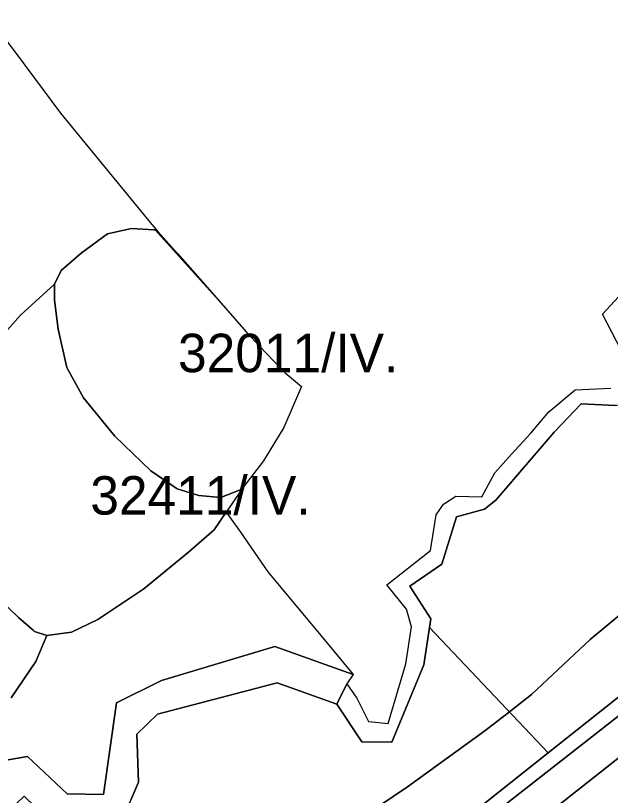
# Model space of a CAD drawing. Extents: x -522079 to -518792, y -1142400 to -1139961.
# Drawn here: x -521597.2 to -521365.3, y -1140523.8 to -1140219.9 of the extents above; entities that cross this region are included whole.
import ezdxf

# ---------------------------------------------------------------- set-up
doc = ezdxf.new("R2010")
doc.units = 0
for name, color, linetype in [('Hranice parcel', 7, 'Continuous'), ('Parcelní čísla', 7, 'Continuous'), ('Poz předměty', 7, 'Continuous'), ('Vnitřní kresba', 7, 'Continuous'), ('Značky bodu BP', 7, 'Continuous')]:
    doc.layers.add(name, color=color, linetype=linetype)

msp = doc.modelspace()

# ---------------------------------------------------------------- linework, layer by layer
at = {"layer": 'Hranice parcel'}
msp.add_lwpolyline([(-521245.45, -1140392.88), (-521233.39, -1140383.74), (-521212.85, -1140368.17), (-521190.73, -1140351.49), (-521181.05, -1140344.19), (-521160.13, -1140329.24), (-521148.51, -1140320.94), (-521130.86, -1140309.33), (-521127.62, -1140312.94), (-521177.32, -1140348.18), (-521510.5, -1140608.85), (-521513.48, -1140605.69), (-521389.53, -1140507.12), (-521274.04, -1140415.55), (-521252.22, -1140398.25)], close=True, dxfattribs=at)
at = {"layer": 'Parcelní čísla'}
msp.add_lwpolyline([(-521608.33, -1140219.87), (-521596.95, -1140234.61), (-521579.62, -1140257.92), (-521560.73, -1140281.01), (-521544.01, -1140301.33), (-521541.69, -1140303.97), (-521534.06, -1140312.64), (-521523.43, -1140324.72), (-521507.29, -1140343.05), (-521499.72, -1140351.14), (-521492.09, -1140359.13), (-521487.26, -1140363.09), (-521485.71, -1140364.38), (-521492.65, -1140380.39), (-521500.52, -1140393.33), (-521508.32, -1140403.51), (-521515.07, -1140413.37), (-521509.46, -1140421.2), (-521498.88, -1140436.59), (-521476.87, -1140463.06), (-521465.61, -1140476.61), (-521496.06, -1140465.78), (-521540.23, -1140479.04), (-521557.78, -1140487.71), (-521562.91, -1140523.45), (-521577.07, -1140523.11), (-521592.51, -1140508.64), (-521606.9, -1140511.13)], dxfattribs=at)
for points in [[(-521042, -1140261.25), (-521029.36, -1140265.01), (-521071.25, -1140292.13), (-521105.44, -1140313.39), (-521138.04, -1140336), (-521166.55, -1140356.84), (-521170.88, -1140360.01), (-521186.8, -1140371.65), (-521202.24, -1140382.94), (-521262.52, -1140430.5), (-521393.25, -1140533.65), (-521431, -1140563.44), (-521501.14, -1140618.78), (-521510.5, -1140608.85), (-521177.32, -1140348.18), (-521127.62, -1140312.94), (-521125.23, -1140315.3), (-521106.97, -1140303.78), (-521080.73, -1140284.42), (-521065.28, -1140272.43), (-521054.61, -1140266.48)], [(-521309.07, -1140623.96), (-521393.25, -1140533.65), (-521262.52, -1140430.5), (-521152, -1140551.52)]]:
    msp.add_lwpolyline(points, close=True, dxfattribs=at)
at = {"layer": 'Poz předměty'}
for points in [[(-521443.44, -1140442.21), (-521430.97, -1140433.67), (-521425.29, -1140415.18), (-521414.4, -1140412.25), (-521409.97, -1140408.74), (-521387.23, -1140382.25), (-521376.68, -1140371.11), (-521363.37, -1140371.78), (-521350.48, -1140368.68), (-521348.98, -1140355.15), (-521360.62, -1140338.49), (-521354.5, -1140332.33), (-521274.04, -1140415.55), (-521389.53, -1140507.12), (-521435.8, -1140458.35), (-521435.3, -1140455)], [(-521389.53, -1140507.12), (-521513.48, -1140605.69), (-521566.82, -1140550.59), (-521584.91, -1140532.83), (-521565.66, -1140535.94), (-521555.6, -1140533.49), (-521549.24, -1140518.67), (-521549.91, -1140499.85), (-521541.79, -1140492.15), (-521495.23, -1140479.84), (-521471.95, -1140488.22), (-521462.16, -1140502.96), (-521450.52, -1140503.04), (-521437.98, -1140472.83), (-521435.8, -1140458.35)]]:
    msp.add_lwpolyline(points, close=True, dxfattribs=at)
at = {"layer": 'Vnitřní kresba'}
for points in [[(-521357.5, -1140357.21), (-521368.43, -1140336.25), (-521357.43, -1140324.38)], [(-521363.37, -1140371.78), (-521376.68, -1140371.11), (-521387.23, -1140382.25), (-521409.97, -1140408.74), (-521414.4, -1140412.25), (-521425.29, -1140415.18), (-521430.97, -1140433.67), (-521443.44, -1140442.21), (-521435.3, -1140455), (-521435.8, -1140458.35), (-521437.98, -1140472.83), (-521450.52, -1140503.04), (-521462.16, -1140502.96), (-521471.95, -1140488.22), (-521468.11, -1140480.32), (-521464.21, -1140485.93), (-521459.62, -1140494.93), (-521451.98, -1140495.75), (-521445.06, -1140472.47), (-521442.88, -1140458.09), (-521444.82, -1140451.17), (-521452.48, -1140441.66), (-521435.44, -1140428.3), (-521433.21, -1140414.4), (-521430.32, -1140410.33), (-521425.52, -1140407.15), (-521415.37, -1140407.41), (-521410.38, -1140398.05), (-521403.86, -1140390.75), (-521396.32, -1140382.62), (-521389.35, -1140374.32), (-521379.07, -1140365.7), (-521365.2, -1140365.12)], [(-521606.9, -1140511.13), (-521592.51, -1140508.64), (-521577.07, -1140523.11), (-521562.91, -1140523.45), (-521557.78, -1140487.71), (-521540.23, -1140479.04), (-521496.06, -1140465.78), (-521465.61, -1140476.61), (-521468.11, -1140480.32), (-521471.95, -1140488.22), (-521495.23, -1140479.84), (-521541.79, -1140492.15), (-521549.91, -1140499.85), (-521549.24, -1140518.67), (-521555.6, -1140533.49), (-521565.66, -1140535.94), (-521584.91, -1140532.83), (-521593.79, -1140524.1), (-521596.8, -1140526.87), (-521598.04, -1140528.01)]]:
    msp.add_lwpolyline(points, dxfattribs=at)
at = {"layer": 'Značky bodu BP'}
for points in [[(-521608.33, -1140219.87), (-521596.95, -1140234.61), (-521579.62, -1140257.92), (-521560.73, -1140281.01), (-521544.01, -1140301.33), (-521541.69, -1140303.97), (-521534.06, -1140312.64), (-521523.43, -1140324.72), (-521519.09, -1140329.65), (-521542.8, -1140303.36), (-521543.3, -1140303.33), (-521551.95, -1140302.78), (-521561.32, -1140304.95), (-521571.66, -1140312.43), (-521579.35, -1140319.18), (-521582, -1140324.49), (-521595.28, -1140336.6), (-521608.32, -1140351.33)], [(-521608.32, -1140351.33), (-521595.28, -1140336.6), (-521582, -1140324.49), (-521582, -1140330.76), (-521580.56, -1140342.09), (-521577.19, -1140357.04), (-521570.7, -1140368.86), (-521558.44, -1140383.81), (-521544.49, -1140397.32), (-521534.16, -1140404.31), (-521525.74, -1140406.96), (-521517.33, -1140407.69), (-521516.94, -1140407.54), (-521509.18, -1140404.57), (-521509, -1140404.5), (-521515.07, -1140413.37), (-521519.72, -1140420.31), (-521529.77, -1140429.03), (-521547.17, -1140443.21), (-521565.11, -1140455.2), (-521575.43, -1140460.11), (-521584.95, -1140461.48), (-521589.84, -1140459.84), (-521590.17, -1140459.55), (-521596.09, -1140454.38), (-521607.23, -1140443.75)], [(-521357.5, -1140357.21), (-521368.43, -1140336.25), (-521357.43, -1140324.38)], [(-521598.91, -1140485.69), (-521589.25, -1140471.59), (-521584.95, -1140461.48), (-521575.43, -1140460.11), (-521565.11, -1140455.2), (-521547.17, -1140443.21), (-521529.77, -1140429.03), (-521519.72, -1140420.31), (-521515.07, -1140413.37), (-521509.46, -1140421.2), (-521498.88, -1140436.59), (-521476.87, -1140463.06), (-521465.61, -1140476.61), (-521468.11, -1140480.32), (-521464.21, -1140485.93), (-521459.62, -1140494.93), (-521451.98, -1140495.75), (-521445.06, -1140472.47), (-521442.88, -1140458.09), (-521444.82, -1140451.17), (-521452.48, -1140441.66), (-521435.44, -1140428.3), (-521433.21, -1140414.4), (-521430.32, -1140410.33), (-521425.52, -1140407.15), (-521415.37, -1140407.41), (-521410.38, -1140398.05), (-521403.86, -1140390.75), (-521396.32, -1140382.62), (-521389.35, -1140374.32), (-521379.07, -1140365.7), (-521365.2, -1140365.12)], [(-521607.23, -1140443.75), (-521596.09, -1140454.38), (-521590.17, -1140459.55), (-521589.84, -1140459.84), (-521584.95, -1140461.48), (-521589.25, -1140471.59), (-521598.91, -1140485.69)], [(-521352.5, -1140445.81), (-521373.25, -1140463.07), (-521396.02, -1140484.39), (-521404.68, -1140491.15), (-521414.24, -1140498.6), (-521444.35, -1140520.43), (-521482.31, -1140546.07)], [(-521482.31, -1140546.07), (-521444.35, -1140520.43), (-521414.24, -1140498.6), (-521404.68, -1140491.15), (-521396.02, -1140484.39), (-521373.25, -1140463.07), (-521352.5, -1140445.81)]]:
    msp.add_lwpolyline(points, dxfattribs=at)
msp.add_lwpolyline([(-521487.26, -1140363.09), (-521485.71, -1140364.38), (-521492.65, -1140380.39), (-521500.52, -1140393.33), (-521508.32, -1140403.51), (-521509, -1140404.5), (-521509.18, -1140404.57), (-521516.94, -1140407.54), (-521517.33, -1140407.69), (-521525.74, -1140406.96), (-521534.16, -1140404.31), (-521544.49, -1140397.32), (-521558.44, -1140383.81), (-521570.7, -1140368.86), (-521577.19, -1140357.04), (-521580.56, -1140342.09), (-521582, -1140330.76), (-521582, -1140324.49), (-521579.35, -1140319.18), (-521571.66, -1140312.43), (-521561.32, -1140304.95), (-521551.95, -1140302.78), (-521543.3, -1140303.33), (-521542.8, -1140303.36), (-521519.09, -1140329.65), (-521507.29, -1140343.05), (-521499.72, -1140351.14), (-521492.09, -1140359.13)], close=True, dxfattribs=at)

# ---------------------------------------------------------------- texts
for s, p in [('32011/IV.', (-521533.85, -1140358.84)), ('32411/IV.', (-521568.04, -1140414.35))]:
    msp.add_text(s, height=15, rotation=0, dxfattribs=at).set_placement(p)

doc.saveas('drawing.dxf')
